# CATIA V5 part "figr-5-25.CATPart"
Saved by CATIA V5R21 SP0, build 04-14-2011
Part number: Part2
Bounding box of the stored display mesh (mm): x -75 to 75, y -62.5 to 62.5, z 0 to 20
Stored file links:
  D:\CATIA V5R21 E-RESOURCES\CATIA-V5R21\catia-v5r21-prt\c05-catia-v5r20-prt\catia-v5r21-figr-5-25.CATPart
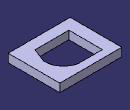
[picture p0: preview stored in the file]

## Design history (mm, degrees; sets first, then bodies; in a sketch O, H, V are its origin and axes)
Body1 (main body)
  Sketch1 on xy-plane, origin (0, 0, 0), H (1, 0, 0), V (0, 1, 0)
    line L1 (-75, 62.5) -> (75, 62.5)
    line L2 (75, 62.5) -> (75, -62.5)
    line L3 (75, -62.5) -> (-75, -62.5)
    line L4 (-75, -62.5) -> (-75, 62.5)
    axis line L5 (75, -62.5) -> (-75, 62.5)
    length L3 = 150
    length L2 = 125
    horizontal: L1 H, L3 H
    vertical: L2 V, L4 V
    midpoint: O L5
  Pad1: profile Sketch1, direction (0, 0, 1), length 20
  Sketch2 on face of Pad1, origin (0, 0, 20), H (1, 0, 0), V (0, 1, 0)
    point P1 (-46.6075, -37.2048)
    line L1 (-46.6075, -37.2048) -> (35.3732, -37.2048)
    point P2 (35.3732, -37.2048)
    point P3 (48.2962, -4.0895)
    line L2 (48.2962, -4.0895) -> (48.2962, 0)
    point P4 (48.2962, 0)
    arc A1 centre (3.919, 0) radius 44.3773 from (48.2962, 0) to (9.9309, 43.9682) ccw
    point P5 (3.919, 0)
    point P6 (9.9309, 43.9682)
    line L3 (9.9309, 43.9682) -> (-46.6075, 43.9682)
    point P7 (-46.6075, 43.9682)
    line L4 (-46.6075, 43.9682) -> (-46.6075, -37.2048)
    line L5 (35.3732, -37.2048) -> (48.2962, -4.0895)
    horizontal: L1 H, L3 H
    coincidence: P4 H
    vertical: L2 V, L4 V
    tangency: A1 L2
    fix: P1, P2, P3, P4, P5, P6, P7, L1, L2, A1, L3, L4, L5
  Pocket1: profile Sketch2, direction (0, 0, -1), through (limit type 3)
